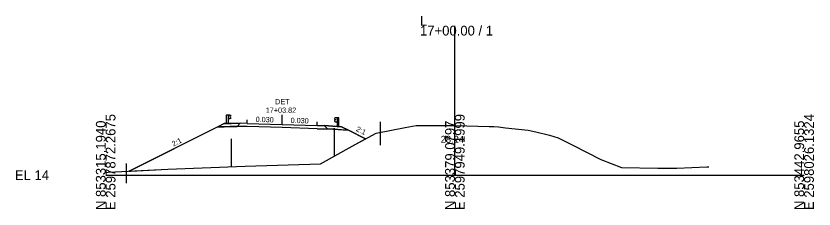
# Model space of a CAD drawing. Extents: x -26 to 1203, y -10 to 9526.
# Drawn here: x -25.7 to 202.8, y 6990.3 to 7045.5 of the extents above; entities that cross this region are included whole.
import ezdxf

# ---------------------------------------------------------------- set-up
doc = ezdxf.new("R2010")
doc.units = 0
for name, color, linetype in [('Exist Cross Section Cell', 7, 'Continuous'), ('Exist XS Center Line Elevation Label', 7, 'Continuous'), ('Exist XS Ground Line', 7, 'Continuous'), ('Prop XS Alignment Label', 7, 'Continuous'), ('Prop XS Earthwork Shape', 7, 'Continuous'), ('Prop XS EOT Tick Mark', 7, 'Continuous'), ('Prop XS Exc Vertical Line 1', 7, 'Continuous'), ('Prop XS Exc Vertical Line 2', 7, 'Continuous'), ('Prop XS Finish Grade', 7, 'Continuous'), ('Prop XS Finish Grade Earthwork', 7, 'Continuous'), ('Prop XS Finish Grade Paved Shoulder', 7, 'Continuous'), ('Prop XS Finish Grade Pavement', 7, 'Continuous'), ('Prop XS Guardrail', 7, 'Continuous'), ('Prop XS Pvmt Edge Slope', 7, 'Continuous'), ('Prop XS SE Text', 7, 'Continuous'), ('Prop XS Side Slope Text', 7, 'Continuous'), ('Prop XS Station Labels', 7, 'Continuous'), ('Prop XS Subgrade Earthwork', 7, 'Continuous'), ('Scratch_Level_1', 7, 'Continuous'), ('Scratch_Level_2', 7, 'Continuous')]:
    doc.layers.add(name, color=color, linetype=linetype)

msp = doc.modelspace()

# ---------------------------------------------------------------- linework, layer by layer
at = {"layer": 'Exist Cross Section Cell'}
for p, q in [((100, 7000), (100, 7042.73)), ((0, 7000), (100, 7000)), ((100, 7000), (200, 7000))]:
    msp.add_line(p, q, dxfattribs=at)
at = {"layer": 'Exist XS Ground Line'}
for p, q in [((85.71, 7013.58), (88.86, 7014.2)), ((88.86, 7014.2), (90.2, 7014.21)), ((90.2, 7014.21), (100.2, 7014.24)), ((100.2, 7014.24), (109.81, 7013.95)), ((109.81, 7013.95), (111.12, 7013.93)), ((111.12, 7013.93), (112.45, 7013.77)), ((112.45, 7013.77), (114.46, 7013.56)), ((70.59, 7008.25), (77.41, 7012.04)), ((77.41, 7012.04), (85.71, 7013.58)), ((114.46, 7013.56), (120.95, 7012.91)), ((120.95, 7012.91), (123.15, 7012.36)), ((123.15, 7012.36), (127.11, 7011.4)), ((127.11, 7011.4), (129.61, 7010.71)), ((129.61, 7010.71), (133.78, 7008.54)), ((61.47, 7003.2), (70.59, 7008.25)), ((133.78, 7008.54), (141.75, 7004.52)), ((17.81, 7001.7), (39.97, 7002.52)), ((39.97, 7002.52), (61.47, 7003.2)), ((141.75, 7004.52), (147.66, 7002.22)), ((163.52, 7002.04), (172.11, 7002.36)), ((172.11, 7002.36), (172.71, 7002.38)), ((0, 7000.77), (0.74, 7000.81)), ((0.74, 7000.81), (17.81, 7001.7)), ((147.66, 7002.22), (158.11, 7002.04)), ((158.11, 7002.04), (163.52, 7002.04))]:
    msp.add_line(p, q, dxfattribs=at)
at = {"layer": 'Prop XS Earthwork Shape'}
msp.add_lwpolyline([(35.65, 7013.92), (33.91, 7013.86), (32.07, 7013.81), (7.19, 7001.36), (6.7, 7001.12), (7.19, 7001.14), (17.81, 7001.7), (39.97, 7002.52), (61.47, 7003.2), (70.59, 7008.25), (74.43, 7010.38), (69.55, 7012.82), (67.48, 7012.99), (65.51, 7013.14), (64.54, 7013.17), (60.56, 7013.29), (50.55, 7013.59), (40.54, 7013.89), (38.54, 7013.95)], close=True, dxfattribs=at)
at = {"layer": 'Prop XS EOT Tick Mark'}
for p, q in [((40.54, 7014.81), (40.54, 7015.81)), ((60.56, 7014.21), (60.56, 7015.21))]:
    msp.add_line(p, q, dxfattribs=at)
at = {"layer": 'Prop XS Exc Vertical Line 1'}
msp.add_line((5.87, 7003.33), (5.87, 6997.75), dxfattribs=at)
at = {"layer": 'Prop XS Exc Vertical Line 2'}
msp.add_line((78.64, 7015.21), (78.64, 7008.53), dxfattribs=at)
at = {"layer": 'Prop XS Finish Grade'}
for p, q in [((33.91, 7014.73), (32.07, 7013.81)), ((35.91, 7014.79), (33.91, 7014.73)), ((38.54, 7014.87), (35.91, 7014.79)), ((62.56, 7014.17), (67.48, 7013.86)), ((67.48, 7013.86), (69.49, 7012.85))]:
    msp.add_line(p, q, dxfattribs=at)
at = {"layer": 'Prop XS Finish Grade Earthwork'}
for p, q in [((32.07, 7013.81), (6.7, 7001.12)), ((69.49, 7012.85), (74.43, 7010.38))]:
    msp.add_line(p, q, dxfattribs=at)
at = {"layer": 'Prop XS Finish Grade Paved Shoulder'}
for p, q in [((40.54, 7014.81), (38.54, 7014.87)), ((60.56, 7014.21), (62.56, 7014.17))]:
    msp.add_line(p, q, dxfattribs=at)
at = {"layer": 'Prop XS Finish Grade Pavement'}
for p, q in [((40.54, 7014.81), (50.55, 7014.51)), ((50.55, 7014.51), (60.56, 7014.21))]:
    msp.add_line(p, q, dxfattribs=at)
at = {"layer": 'Prop XS Guardrail'}
for p, q in [((34.59, 7017.25), (35.09, 7017.25)), ((34.59, 7014.75), (34.59, 7017.25)), ((35.09, 7017.25), (35.59, 7017.25)), ((35.09, 7017.25), (35.09, 7014.75)), ((35.59, 7016.11), (35.09, 7016.11)), ((35.59, 7017.25), (35.88, 7017.05)), ((35.88, 7016.93), (35.59, 7016.73)), ((35.59, 7016.73), (35.59, 7016.63)), ((35.59, 7016.63), (35.88, 7016.43)), ((35.88, 7016.31), (35.59, 7016.11)), ((35.88, 7017.05), (35.91, 7016.99)), ((35.91, 7016.99), (35.88, 7016.93)), ((35.88, 7016.43), (35.91, 7016.37)), ((35.91, 7016.37), (35.88, 7016.31)), ((65.51, 7016.21), (65.48, 7016.15)), ((65.48, 7016.15), (65.51, 7016.09)), ((65.8, 7016.41), (65.51, 7016.21)), ((65.51, 7016.09), (65.8, 7015.89)), ((66.3, 7016.41), (65.8, 7016.41)), ((66.8, 7016.41), (66.3, 7016.41)), ((66.3, 7016.41), (66.3, 7013.91)), ((66.8, 7013.91), (66.8, 7016.41)), ((65.51, 7015.6), (65.48, 7015.54)), ((65.48, 7015.54), (65.51, 7015.48)), ((65.8, 7015.8), (65.51, 7015.6)), ((65.51, 7015.48), (65.8, 7015.28)), ((65.8, 7015.89), (65.8, 7015.8)), ((65.8, 7015.28), (66.3, 7015.28))]:
    msp.add_line(p, q, dxfattribs=at)
at = {"layer": 'Prop XS Pvmt Edge Slope'}
for p, q in [((38.54, 7014.87), (37.61, 7013.94)), ((62.56, 7014.17), (63.49, 7013.23))]:
    msp.add_line(p, q, dxfattribs=at)
at = {"layer": 'Prop XS Side Slope Text'}
msp.add_line((50.55, 7014.51), (50.55, 7017.24), dxfattribs=at)
at = {"layer": 'Prop XS Subgrade Earthwork'}
for p, q in [((33.91, 7013.86), (32.07, 7013.81)), ((35.65, 7013.92), (33.91, 7013.86)), ((38.54, 7013.95), (35.65, 7013.92)), ((40.54, 7013.89), (38.54, 7013.95)), ((50.55, 7013.59), (40.54, 7013.89)), ((60.56, 7013.29), (50.55, 7013.59)), ((60.56, 7013.29), (63.49, 7013.23)), ((63.49, 7013.23), (69.49, 7012.85))]:
    msp.add_line(p, q, dxfattribs=at)
at = {"layer": 'Scratch_Level_1'}
for points in [[(37.61, 7013.94), (35.65, 7013.92), (33.91, 7013.86), (32.07, 7013.81), (33.91, 7014.73), (35.91, 7014.79), (38.54, 7014.87)], [(33.91, 7014.73), (32.07, 7013.81), (33.91, 7013.86), (35.65, 7013.92), (37.61, 7013.94), (38.54, 7014.87), (35.91, 7014.79)], [(63.49, 7013.23), (69.49, 7012.85), (67.48, 7013.86), (62.56, 7014.17)], [(62.56, 7014.17), (63.49, 7013.23), (69.49, 7012.85), (67.48, 7013.86)]]:
    msp.add_lwpolyline(points, close=True, dxfattribs=at)
at = {"layer": 'Scratch_Level_2'}
for p, q in [((65.47, 7013.41), (65.47, 7005.41)), ((35.91, 7010.37), (35.91, 7002.37))]:
    msp.add_line(p, q, dxfattribs=at)

# ---------------------------------------------------------------- texts
at = {"layer": 'Exist Cross Section Cell'}
for s, p in [('L', (90, 7042.73)), ('17+00.00 / 1', (90, 7039.93)), ('EL 14', (-26, 6998.6))]:
    msp.add_text(s, height=2.8, dxfattribs=at).set_placement(p)
for s, p in [('E 2597872.2675', (2.8, 6990)), ('E 2597949.1999', (102.8, 6990)), ('E 2598026.1324', (202.8, 6990)), ('N 853315.1940', (0, 6990)), ('N 853379.0797', (100, 6990)), ('N 853442.9655', (200, 6990))]:
    msp.add_text(s, height=2.8, rotation=90, dxfattribs=at).set_placement(p)
at = {"layer": 'Exist XS Center Line Elevation Label'}
msp.add_text('28.24', height=2, dxfattribs=at).set_placement((95.93, 7009.24))
at = {"layer": 'Prop XS Alignment Label'}
msp.add_text('DET', height=1.5, dxfattribs=at).set_placement((48.52, 7020.26))
at = {"layer": 'Prop XS SE Text'}
for rotation, p in [(358.2898, (42.92, 7015.23)), (358.29, (52.93, 7014.94))]:
    msp.add_text('0.030', height=1.5, rotation=rotation, dxfattribs=at).set_placement(p)
at = {"layer": 'Prop XS Side Slope Text'}
for rotation, p in [(333.4349, (71.54, 7012.7)), (26.5651, (19.4, 7008.14))]:
    msp.add_text('2:1', height=1.5, rotation=rotation, dxfattribs=at).set_placement(p)
at = {"layer": 'Prop XS Station Labels'}
msp.add_text('17+03.82', height=1.5, dxfattribs=at).set_placement((45.84, 7017.83))

doc.saveas('drawing.dxf')
